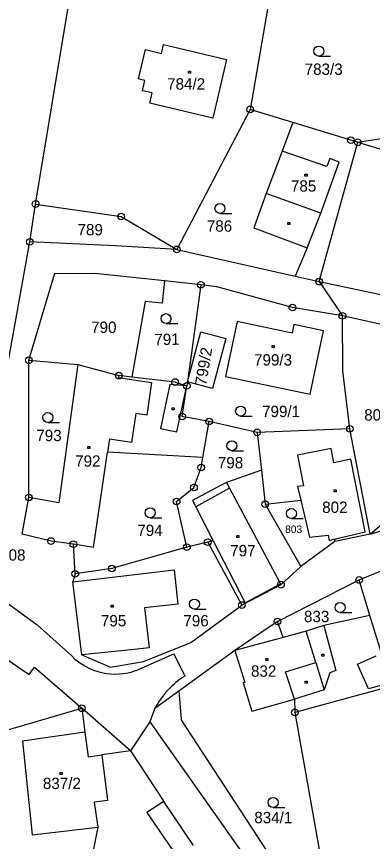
# Model space of a CAD drawing. Extents: x -468021 to -466942, y -1130484 to -1128584.
# Drawn here: x -467224.2 to -467170.9, y -1129029.6 to -1128906.2 of the extents above; entities that cross this region are included whole.
import ezdxf

# ---------------------------------------------------------------- set-up
doc = ezdxf.new("R2010")
doc.units = 0
doc.layers.add('DKM', color=7, linetype='Continuous')

msp = doc.modelspace()

# ---------------------------------------------------------------- linework, layer by layer
at = {"layer": 'DKM'}
for p, q in [((-467221.35, -1128934.27), (-467215.03, -1128896.13)), ((-467185.94, -1128900.9), (-467189.25, -1128920.11)), ((-467202.53, -1128911.73), (-467202.22, -1128910.42)), ((-467202.22, -1128910.42), (-467192.79, -1128912.65)), ((-467205.96, -1128915.56), (-467204.93, -1128911.17)), ((-467204.93, -1128911.17), (-467202.53, -1128911.73)), ((-467192.79, -1128912.65), (-467194.84, -1128921.41)), ((-467178.98, -1128912.14), (-467177.23, -1128912.14)), ((-467198.49, -1128914.39), (-467198.19, -1128914.39)), ((-467198.49, -1128914.69), (-467198.49, -1128914.39)), ((-467198.19, -1128914.69), (-467198.49, -1128914.69)), ((-467198.19, -1128914.39), (-467198.19, -1128914.69)), ((-467205.01, -1128915.78), (-467205.96, -1128915.56)), ((-467205.37, -1128917.32), (-467205.01, -1128915.78)), ((-467203.91, -1128917.66), (-467205.37, -1128917.32)), ((-467204.27, -1128919.2), (-467203.91, -1128917.66)), ((-467194.84, -1128921.41), (-467204.27, -1128919.2)), ((-467189.25, -1128920.11), (-467200.22, -1128941.06)), ((-467182.85, -1128922.07), (-467189.25, -1128920.11)), ((-467182.85, -1128922.07), (-467184.47, -1128926.35)), ((-467174.19, -1128924.71), (-467182.85, -1128922.07)), ((-467173.14, -1128925.04), (-467158.71, -1128922.7)), ((-467178.94, -1128945.88), (-467173.14, -1128925.04)), ((-467173.14, -1128925.04), (-467174.19, -1128924.71)), ((-467173.14, -1128925.04), (-467157.91, -1128929.63)), ((-467184.47, -1128926.35), (-467186.87, -1128932.69)), ((-467177.76, -1128928.67), (-467184.47, -1128926.35)), ((-467177.32, -1128927.47), (-467177.76, -1128928.67)), ((-467175.94, -1128927.99), (-467177.32, -1128927.47)), ((-467178.7, -1128935.63), (-467175.94, -1128927.99)), ((-467181.05, -1128929.81), (-467180.75, -1128929.81)), ((-467181.05, -1128930.11), (-467181.05, -1128929.81)), ((-467180.75, -1128930.11), (-467181.05, -1128930.11)), ((-467180.75, -1128929.81), (-467180.75, -1128930.11)), ((-467186.87, -1128932.69), (-467188.7, -1128937.81)), ((-467178.7, -1128935.63), (-467186.87, -1128932.69)), ((-467222.21, -1128939.94), (-467221.35, -1128934.27)), ((-467221.35, -1128934.27), (-467208.56, -1128936.13)), ((-467208.56, -1128936.13), (-467200.22, -1128941.06)), ((-467193.77, -1128935.68), (-467192.02, -1128935.68)), ((-467180.74, -1128940.83), (-467178.7, -1128935.63)), ((-467183.63, -1128937.02), (-467183.33, -1128937.02)), ((-467183.63, -1128937.32), (-467183.63, -1128937.02)), ((-467183.33, -1128937.32), (-467183.63, -1128937.32)), ((-467183.33, -1128937.02), (-467183.33, -1128937.32)), ((-467188.7, -1128937.81), (-467180.74, -1128940.83)), ((-467228.08, -1128972.35), (-467222.21, -1128939.94)), ((-467209.42, -1128940.55), (-467222.21, -1128939.94)), ((-467200.22, -1128941.06), (-467209.42, -1128940.55)), ((-467200.22, -1128941.06), (-467182.54, -1128945.06)), ((-467180.74, -1128940.83), (-467182.54, -1128945.06)), ((-467222.36, -1128957.65), (-467218.46, -1128944.6)), ((-467218.46, -1128944.6), (-467212.51, -1128944.67)), ((-467202.07, -1128945.78), (-467212.51, -1128944.67)), ((-467182.54, -1128945.06), (-467178.94, -1128945.88)), ((-467202.07, -1128945.78), (-467202.44, -1128949.1)), ((-467196.62, -1128946.36), (-467202.07, -1128945.78)), ((-467178.94, -1128945.88), (-467163.24, -1128949.18)), ((-467178.94, -1128945.88), (-467175.46, -1128950.99)), ((-467196.62, -1128946.36), (-467198.63, -1128960.89)), ((-467194.23, -1128946.65), (-467196.62, -1128946.36)), ((-467182.94, -1128949.75), (-467194.23, -1128946.65)), ((-467204.98, -1128948.85), (-467206.96, -1128960.16)), ((-467202.44, -1128949.1), (-467204.98, -1128948.85)), ((-467175.46, -1128950.99), (-467182.94, -1128949.75)), ((-467175.37, -1128959.25), (-467175.46, -1128950.99)), ((-467164.1, -1128953.5), (-467175.46, -1128950.99)), ((-467201.84, -1128952.17), (-467200.09, -1128952.17)), ((-467191.19, -1128951.85), (-467192.94, -1128960.09)), ((-467182.98, -1128953.57), (-467191.19, -1128951.85)), ((-467182.73, -1128952.3), (-467182.98, -1128953.57)), ((-467178.3, -1128953.23), (-467182.73, -1128952.3)), ((-467198.63, -1128960.89), (-467196.63, -1128953.4)), ((-467196.63, -1128953.4), (-467192.91, -1128954.39)), ((-467180.3, -1128962.74), (-467178.3, -1128953.23)), ((-467192.91, -1128954.39), (-467194.91, -1128961.88)), ((-467185.98, -1128955.43), (-467185.68, -1128955.43)), ((-467185.98, -1128955.73), (-467185.98, -1128955.43)), ((-467185.68, -1128955.73), (-467185.98, -1128955.73)), ((-467185.68, -1128955.43), (-467185.68, -1128955.73)), ((-467222.36, -1128978.18), (-467222.36, -1128957.65)), ((-467222.36, -1128957.65), (-467215.05, -1128958.28)), ((-467215.05, -1128958.28), (-467217.89, -1128978.99)), ((-467215.05, -1128958.28), (-467208.9, -1128959.94)), ((-467174.34, -1128967.91), (-467175.37, -1128959.25)), ((-467208.9, -1128959.94), (-467208.94, -1128960.24)), ((-467208.94, -1128960.24), (-467204.01, -1128960.96)), ((-467206.96, -1128960.16), (-467208.9, -1128959.94)), ((-467200.49, -1128960.91), (-467206.96, -1128960.16)), ((-467204.01, -1128960.96), (-467204.73, -1128965.85)), ((-467200.49, -1128960.91), (-467198.71, -1128961.48)), ((-467198.63, -1128960.89), (-467198.71, -1128961.48)), ((-467194.91, -1128961.88), (-467198.63, -1128960.89)), ((-467192.94, -1128960.09), (-467180.3, -1128962.74)), ((-467201.26, -1128961.28), (-467202.69, -1128967.87)), ((-467198.71, -1128961.48), (-467201.26, -1128961.28)), ((-467200.21, -1128968.37), (-467198.71, -1128961.48)), ((-467199.41, -1128966.05), (-467198.71, -1128961.48)), ((-467200.93, -1128964.76), (-467200.63, -1128964.76)), ((-467200.93, -1128965.06), (-467200.93, -1128964.76)), ((-467200.63, -1128964.76), (-467200.63, -1128965.06)), ((-467206.35, -1128965.61), (-467206.99, -1128969.93)), ((-467204.73, -1128965.85), (-467206.35, -1128965.61)), ((-467200.63, -1128965.06), (-467200.93, -1128965.06)), ((-467195.4, -1128966.82), (-467199.41, -1128966.05)), ((-467190.68, -1128966), (-467188.93, -1128966)), ((-467219.52, -1128966.97), (-467217.77, -1128966.97)), ((-467196.32, -1128972.21), (-467195.4, -1128966.82)), ((-467188.21, -1128968.43), (-467195.4, -1128966.82)), ((-467202.69, -1128967.87), (-467200.21, -1128968.37)), ((-467174.34, -1128967.91), (-467188.21, -1128968.43)), ((-467188.21, -1128968.43), (-467187.57, -1128974.11)), ((-467171.31, -1128983.64), (-467174.34, -1128967.91)), ((-467210.3, -1128969.44), (-467210.59, -1128971.39)), ((-467206.99, -1128969.93), (-467210.3, -1128969.44)), ((-467213.55, -1128970.54), (-467213.25, -1128970.54)), ((-467213.55, -1128970.84), (-467213.55, -1128970.54)), ((-467213.25, -1128970.84), (-467213.55, -1128970.84)), ((-467213.25, -1128970.54), (-467213.25, -1128970.84)), ((-467177.15, -1128970.86), (-467182.15, -1128971.83)), ((-467176.74, -1128972.99), (-467177.15, -1128970.86)), ((-467212.69, -1128985.65), (-467210.59, -1128971.39)), ((-467196.32, -1128972.21), (-467210.59, -1128971.39)), ((-467196.58, -1128973.7), (-467196.32, -1128972.21)), ((-467191.98, -1128971.18), (-467190.23, -1128971.18)), ((-467182.15, -1128971.83), (-467181.26, -1128976.44)), ((-467174.2, -1128972.43), (-467176.74, -1128972.99)), ((-467172.04, -1128983.32), (-467174.2, -1128972.43)), ((-467197.66, -1128976.67), (-467196.58, -1128973.7)), ((-467187.57, -1128974.11), (-467192.8, -1128975.91)), ((-467187.57, -1128974.11), (-467187, -1128979.18)), ((-467192.8, -1128975.91), (-467193.69, -1128976.38)), ((-467192.8, -1128975.91), (-467192.33, -1128976.8)), ((-467200.26, -1128978.78), (-467197.66, -1128976.67)), ((-467193.69, -1128976.38), (-467197.9, -1128978.61)), ((-467192.33, -1128976.8), (-467197.37, -1128979.57)), ((-467192.33, -1128976.8), (-467184.74, -1128991.1)), ((-467181.26, -1128976.44), (-467182.17, -1128976.55)), ((-467182.17, -1128976.55), (-467181.69, -1128978.56)), ((-467176.7, -1128977.01), (-467176.4, -1128977.01)), ((-467176.7, -1128977.31), (-467176.7, -1128977.01)), ((-467176.4, -1128977.01), (-467176.4, -1128977.31)), ((-467223.35, -1128983.65), (-467222.36, -1128978.18)), ((-467217.89, -1128978.99), (-467222.36, -1128978.18)), ((-467176.4, -1128977.31), (-467176.7, -1128977.31)), ((-467198.71, -1128985.6), (-467200.26, -1128978.78)), ((-467197.9, -1128978.61), (-467197.37, -1128979.57)), ((-467197.37, -1128979.57), (-467194.77, -1128984.66)), ((-467187, -1128979.18), (-467181.69, -1128978.56)), ((-467187, -1128979.18), (-467181.69, -1128988.49)), ((-467181.69, -1128978.56), (-467180.38, -1128984.11)), ((-467171.31, -1128983.64), (-467166.54, -1128979.57)), ((-467171.31, -1128983.64), (-467157.94, -1128979.62)), ((-467204.21, -1128981.21), (-467202.46, -1128981.21)), ((-467183.08, -1128981.33), (-467181.33, -1128981.33)), ((-467176.69, -1128984.43), (-467172.04, -1128983.32)), ((-467219.05, -1128984.69), (-467223.35, -1128983.65)), ((-467191.27, -1128983.88), (-467190.97, -1128983.88)), ((-467191.27, -1128984.18), (-467191.27, -1128983.88)), ((-467190.97, -1128984.18), (-467191.27, -1128984.18)), ((-467190.97, -1128983.88), (-467190.97, -1128984.18)), ((-467180.38, -1128984.11), (-467177.6, -1128983.79)), ((-467177.6, -1128983.79), (-467177.41, -1128984.6)), ((-467177.41, -1128984.6), (-467176.69, -1128984.43)), ((-467176.69, -1128984.43), (-467176.61, -1128984.75)), ((-467171.31, -1128983.64), (-467176.61, -1128984.75)), ((-467215.71, -1128985.15), (-467219.05, -1128984.69)), ((-467212.69, -1128985.65), (-467215.71, -1128985.15)), ((-467215.42, -1128989.59), (-467215.71, -1128985.15)), ((-467198.71, -1128985.6), (-467209.95, -1128988.8)), ((-467195.61, -1128984.86), (-467198.71, -1128985.6)), ((-467194.77, -1128984.66), (-467195.61, -1128984.86)), ((-467195.61, -1128984.86), (-467190.49, -1128994.27)), ((-467194.77, -1128984.66), (-467190.02, -1128993.95)), ((-467176.61, -1128984.75), (-467181.69, -1128988.49)), ((-467172.95, -1128990.52), (-467162.33, -1128986.09)), ((-467209.95, -1128988.8), (-467215.42, -1128989.59)), ((-467207.78, -1128989.87), (-467200.64, -1128989.01)), ((-467200.64, -1128989.01), (-467200.06, -1128994.12)), ((-467181.69, -1128988.49), (-467184.65, -1128991.22)), ((-467215.42, -1128989.59), (-467215.77, -1128990.79)), ((-467215.77, -1128990.79), (-467207.78, -1128989.87)), ((-467185.16, -1128996.73), (-467172.95, -1128990.52)), ((-467171.33, -1128995.85), (-467172.95, -1128990.52)), ((-467214.46, -1129001.73), (-467215.77, -1128990.79)), ((-467184.65, -1128991.22), (-467190.49, -1128994.27)), ((-467190.02, -1128993.95), (-467184.74, -1128991.1)), ((-467210.03, -1128994.3), (-467209.73, -1128994.3)), ((-467210.03, -1128994.6), (-467210.03, -1128994.3)), ((-467209.73, -1128994.3), (-467209.73, -1128994.6)), ((-467200.06, -1128994.12), (-467205.05, -1128994.69)), ((-467198.12, -1128999.85), (-467190.49, -1128994.27)), ((-467209.73, -1128994.6), (-467210.03, -1128994.6)), ((-467205.05, -1128994.69), (-467204.37, -1129000.68)), ((-467197.6, -1128994.87), (-467195.85, -1128994.87)), ((-467175.8, -1128995.37), (-467174.05, -1128995.37)), ((-467185.16, -1128996.73), (-467191.55, -1129001.06)), ((-467184.32, -1128999.11), (-467185.16, -1128996.73)), ((-467171.33, -1128995.85), (-467178.24, -1128997.33)), ((-467168.38, -1129005.51), (-467171.33, -1128995.85)), ((-467178.24, -1128997.33), (-467180.85, -1128998.17)), ((-467178.24, -1128997.33), (-467176.45, -1129004.05)), ((-467184.32, -1128999.11), (-467191.55, -1129001.06)), ((-467180.85, -1128998.17), (-467184.32, -1128999.11)), ((-467179.41, -1129002.87), (-467180.85, -1128998.17)), ((-467205.19, -1129002.71), (-467198.12, -1128999.85)), ((-467206.62, -1129000.9), (-467214.46, -1129001.73)), ((-467214.46, -1129001.73), (-467210.16, -1129003.56)), ((-467204.37, -1129000.68), (-467206.62, -1129000.9)), ((-467199.92, -1129007.12), (-467191.73, -1129001.18)), ((-467191.55, -1129001.06), (-467191.73, -1129001.18)), ((-467191.55, -1129001.06), (-467190.06, -1129005.85)), ((-467178.52, -1129001.61), (-467178.22, -1129001.61)), ((-467178.52, -1129001.91), (-467178.52, -1129001.61)), ((-467178.22, -1129001.61), (-467178.22, -1129001.91)), ((-467210.16, -1129003.56), (-467205.19, -1129002.71)), ((-467186.93, -1129002.27), (-467186.63, -1129002.27)), ((-467186.93, -1129002.57), (-467186.93, -1129002.27)), ((-467186.63, -1129002.57), (-467186.93, -1129002.57)), ((-467186.63, -1129002.27), (-467186.63, -1129002.57)), ((-467183.98, -1129004.24), (-467179.41, -1129002.87)), ((-467179.41, -1129002.87), (-467178.19, -1129006.93)), ((-467178.22, -1129001.91), (-467178.52, -1129001.91)), ((-467173.17, -1129003.12), (-467170.41, -1129001.89)), ((-467182.62, -1129008.35), (-467183.98, -1129004.24)), ((-467176.45, -1129004.05), (-467177.32, -1129004.39)), ((-467171.53, -1129006.8), (-467173.17, -1129003.12)), ((-467177.32, -1129004.39), (-467178.19, -1129006.93)), ((-467190.06, -1129005.85), (-467190.3, -1129005.92)), ((-467190.3, -1129005.92), (-467188.98, -1129010.16)), ((-467168.1, -1129006.43), (-467182.57, -1129010.33)), ((-467181.01, -1129005.66), (-467180.71, -1129005.66)), ((-467181.01, -1129005.96), (-467181.01, -1129005.66)), ((-467180.71, -1129005.96), (-467181.01, -1129005.96)), ((-467180.71, -1129005.66), (-467180.71, -1129005.96)), ((-467168.59, -1129006.02), (-467171.53, -1129006.8)), ((-467203.5, -1129009.71), (-467199.92, -1129007.12)), ((-467199.92, -1129007.12), (-467199.59, -1129011.4)), ((-467178.19, -1129006.93), (-467182.62, -1129008.35)), ((-467188.98, -1129010.16), (-467182.62, -1129008.35)), ((-467182.62, -1129008.35), (-467182.57, -1129010.33)), ((-467234.4, -1129015.48), (-467214.43, -1129009.71)), ((-467207.14, -1129016.06), (-467214.43, -1129009.71)), ((-467214.43, -1129009.71), (-467214, -1129013.29)), ((-467203.5, -1129009.71), (-467204.28, -1129011.72)), ((-467182.57, -1129010.33), (-467176.75, -1129043.1)), ((-467204.28, -1129011.72), (-467207.14, -1129016.06)), ((-467204.28, -1129011.72), (-467181.34, -1129044.17)), ((-467178.55, -1129043.52), (-467199.59, -1129011.4)), ((-467214, -1129013.29), (-467223.34, -1129014.61)), ((-467214, -1129013.29), (-467213.51, -1129016.97)), ((-467223.34, -1129014.61), (-467221.86, -1129028.63)), ((-467207.14, -1129016.06), (-467211.43, -1129016.69)), ((-467207.14, -1129016.06), (-467202.18, -1129023.64)), ((-467213.51, -1129016.97), (-467211.43, -1129016.69)), ((-467211.43, -1129016.69), (-467210.58, -1129023.53)), ((-467217.7, -1129019.33), (-467217.4, -1129019.33)), ((-467217.7, -1129019.63), (-467217.7, -1129019.33)), ((-467217.4, -1129019.63), (-467217.7, -1129019.63)), ((-467217.4, -1129019.33), (-467217.4, -1129019.63)), ((-467210.58, -1129023.53), (-467212.57, -1129023.78)), ((-467212.57, -1129023.78), (-467212.03, -1129027.51)), ((-467202.18, -1129023.64), (-467204.72, -1129025.33)), ((-467197.71, -1129030.24), (-467202.18, -1129023.64)), ((-467185.82, -1129024.56), (-467184.07, -1129024.56)), ((-467204.72, -1129025.33), (-467200.2, -1129031.96)), ((-467221.86, -1129028.63), (-467212.03, -1129027.51)), ((-467212.03, -1129027.51), (-467216.26, -1129048.14))]:
    msp.add_line(p, q, dxfattribs=at)
for points in [[(-467225.98, -1128993.68), (-467221.14, -1128997.23), (-467215.96, -1129001.89)], [(-467206.3, -1129004.04), (-467200.66, -1129001.59), (-467199.04, -1129004.89)], [(-467226.26, -1129001.95), (-467222.32, -1129004.68), (-467221.52, -1129003.54), (-467214.43, -1129009.71)]]:
    msp.add_lwpolyline(points, dxfattribs=at)
for centre, radius in [((-467178.98, -1128911.39), 0.75), ((-467189.25, -1128920.11), 0.5), ((-467189.25, -1128920.11), 0.01), ((-467174.19, -1128924.71), 0.5), ((-467174.19, -1128924.71), 0.01), ((-467173.14, -1128925.04), 0.5), ((-467173.14, -1128925.04), 0.01), ((-467221.35, -1128934.27), 0.5), ((-467221.35, -1128934.27), 0.01), ((-467193.77, -1128934.93), 0.75), ((-467208.56, -1128936.13), 0.5), ((-467208.56, -1128936.13), 0.01), ((-467222.21, -1128939.94), 0.5), ((-467222.21, -1128939.94), 0.01), ((-467200.22, -1128941.06), 0.5), ((-467200.22, -1128941.06), 0.01), ((-467196.62, -1128946.36), 0.5), ((-467178.94, -1128945.88), 0.5), ((-467178.94, -1128945.88), 0.01), ((-467196.62, -1128946.36), 0.01), ((-467182.94, -1128949.75), 0.5), ((-467182.94, -1128949.75), 0.01), ((-467201.84, -1128951.42), 0.75), ((-467175.46, -1128950.99), 0.5), ((-467175.46, -1128950.99), 0.01), ((-467222.36, -1128957.65), 0.5), ((-467222.36, -1128957.65), 0.01), ((-467208.9, -1128959.94), 0.5), ((-467208.9, -1128959.94), 0.01), ((-467200.49, -1128960.91), 0.5), ((-467200.49, -1128960.91), 0.01), ((-467198.71, -1128961.48), 0.5), ((-467198.71, -1128961.48), 0.01), ((-467190.68, -1128965.25), 0.75), ((-467219.52, -1128966.22), 0.75), ((-467199.41, -1128966.05), 0.5), ((-467199.41, -1128966.05), 0.01), ((-467195.4, -1128966.82), 0.5), ((-467195.4, -1128966.82), 0.01), ((-467188.21, -1128968.43), 0.5), ((-467188.21, -1128968.43), 0.01), ((-467174.34, -1128967.91), 0.5), ((-467174.34, -1128967.91), 0.01), ((-467191.98, -1128970.43), 0.75), ((-467196.58, -1128973.7), 0.5), ((-467196.58, -1128973.7), 0.01), ((-467197.66, -1128976.67), 0.5), ((-467197.66, -1128976.67), 0.01), ((-467222.36, -1128978.18), 0.5), ((-467222.36, -1128978.18), 0.01), ((-467200.26, -1128978.78), 0.5), ((-467200.26, -1128978.78), 0.01), ((-467187, -1128979.18), 0.5), ((-467187, -1128979.18), 0.01), ((-467204.21, -1128980.46), 0.75), ((-467183.08, -1128980.58), 0.75), ((-467219.05, -1128984.69), 0.5), ((-467195.61, -1128984.86), 0.5), ((-467219.05, -1128984.69), 0.01), ((-467215.71, -1128985.15), 0.5), ((-467215.71, -1128985.15), 0.01), ((-467198.71, -1128985.6), 0.5), ((-467198.71, -1128985.6), 0.01), ((-467195.61, -1128984.86), 0.01), ((-467215.42, -1128989.59), 0.5), ((-467209.95, -1128988.8), 0.5), ((-467209.95, -1128988.8), 0.01), ((-467215.42, -1128989.59), 0.01), ((-467184.65, -1128991.22), 0.5), ((-467172.95, -1128990.52), 0.5), ((-467172.95, -1128990.52), 0.01), ((-467184.65, -1128991.22), 0.01), ((-467197.6, -1128994.12), 0.75), ((-467190.49, -1128994.27), 0.5), ((-467190.49, -1128994.27), 0.01), ((-467175.8, -1128994.62), 0.75), ((-467185.16, -1128996.73), 0.5), ((-467185.16, -1128996.73), 0.01), ((-467214.43, -1129009.71), 0.5), ((-467214.43, -1129009.71), 0.01), ((-467182.57, -1129010.33), 0.5), ((-467182.57, -1129010.33), 0.01), ((-467185.82, -1129023.81), 0.75)]:
    msp.add_circle(centre, radius, dxfattribs=at)
for centre, radius, start, end in [((-467209.44, -1128995.39), 9.2, 224.9194, 289.9853), ((-467191.94, -1129015.93), 13.13, 122.7405, 151.7027)]:
    msp.add_arc(centre, radius, start, end, dxfattribs=at)

# ---------------------------------------------------------------- texts
for s, height, p in [('783/3', 1.7, (-467181.1, -1128914.95)), ('784/2', 1.7, (-467201.68, -1128917.15)), ('785', 1.7, (-467183.15, -1128932.42)), ('789', 1.7, (-467215.08, -1128938.96)), ('786', 1.7, (-467195.74, -1128938.41)), ('790', 1.7, (-467213.05, -1128953.56)), ('799/3', 1.7, (-467188.67, -1128958.44)), ('799/1', 1.7, (-467187.47, -1128966.15)), ('804/2', 1.7, (-467172.19, -1128966.67)), ('793', 1.7, (-467221.25, -1128969.75)), ('792', 1.7, (-467215.44, -1128973.57)), ('798', 1.7, (-467194.09, -1128973.82)), ('802', 1.7, (-467178.48, -1128980.49)), ('794', 1.7, (-467206.14, -1128983.94)), ('803', 1.14, (-467184.02, -1128983.5)), ('797', 1.7, (-467192.24, -1128986.98)), ('808', 1.7, (-467226.66, -1128987.63)), ('833', 1.7, (-467181.2, -1128996.83)), ('795', 1.7, (-467211.58, -1128997.46)), ('796', 1.7, (-467199.25, -1128997.46)), ('832', 1.7, (-467189.13, -1129005)), ('837/2', 1.7, (-467220.27, -1129021.8)), ('834/1', 1.7, (-467188.64, -1129026.91))]:
    msp.add_text(s, height=height, dxfattribs=at).set_placement(p)
for s, rotation, p in [('791', 1.3243, (-467203.57, -1128955.41)), ('799/2', 80.5377, (-467195.85, -1128961.49))]:
    msp.add_text(s, height=1.7, rotation=rotation, dxfattribs=at).set_placement(p)

doc.saveas('drawing.dxf')
